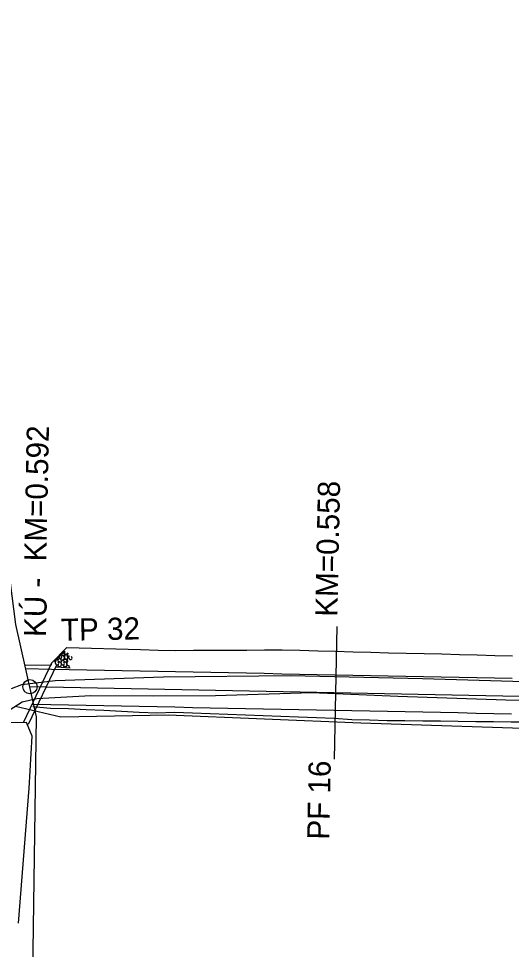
# Model space of a CAD drawing. Extents: x -478000 to -474772, y -1116940 to -1114124.
# Drawn here: x -477821.2 to -477765.6, y -1116669 to -1116563.9 of the extents above; entities that cross this region are included whole.
import ezdxf

# ---------------------------------------------------------------- set-up
doc = ezdxf.new("R2010")
doc.units = 0
for name, color, linetype in [('1', 7, 'Continuous'), ('hrana_P', 7, 'Continuous'), ('L', 7, 'Continuous'), ('ObPÚ', 7, 'Continuous'), ('POLYGONY_SITUACE_PF', 7, 'Continuous'), ('POLYGONY_SITUACE_PF_POPISY', 7, 'Continuous'), ('POLYGONY_SITUACE_PO', 7, 'Continuous'), ('popis', 7, 'Continuous'), ('TP_HS', 7, 'Continuous')]:
    doc.layers.add(name, color=color, linetype=linetype)

msp = doc.modelspace()

# ---------------------------------------------------------------- linework, layer by layer
at = {"layer": '1'}
for p, q in [((-477817.51878495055, -1116636.6520980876), (-477820.70846817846, -1116643.3293213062)), ((-477816.97738545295, -1116636.9107224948), (-477820.16706868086, -1116643.5879457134))]:
    msp.add_line(p, q, dxfattribs=at)
at = {"layer": 'hrana_P'}
for p, q in [((-477819.63, -1116641.574), (-477817.63300000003, -1116641.747)), ((-477817.63300000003, -1116641.747), (-477815.63400000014, -1116641.791)), ((-477815.63400000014, -1116641.791), (-477813.6350000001, -1116641.878)), ((-477813.6350000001, -1116641.878), (-477811.63700000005, -1116641.979)), ((-477811.63700000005, -1116641.979), (-477809.639, -1116642.0790000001)), ((-477809.639, -1116642.0790000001), (-477807.64, -1116642.179)), ((-477807.64, -1116642.179), (-477805.64200000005, -1116642.2790000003)), ((-477805.64200000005, -1116642.2790000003), (-477803.64, -1116642.2)), ((-477803.64, -1116642.2), (-477801.641, -1116642.2680000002)), ((-477801.641, -1116642.2680000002), (-477799.64200000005, -1116642.344)), ((-477799.64200000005, -1116642.344), (-477797.64300000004, -1116642.4200000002)), ((-477797.64300000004, -1116642.4200000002), (-477795.64400000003, -1116642.496)), ((-477795.64400000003, -1116642.496), (-477793.645, -1116642.5720000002)), ((-477793.645, -1116642.5720000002), (-477791.646, -1116642.649)), ((-477791.646, -1116642.649), (-477789.647, -1116642.725)), ((-477789.647, -1116642.725), (-477787.64900000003, -1116642.801)), ((-477787.64900000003, -1116642.801), (-477785.65, -1116642.877)), ((-477785.65, -1116642.877), (-477783.652, -1116643.0120000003)), ((-477783.652, -1116643.0120000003), (-477781.65300000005, -1116643.08)), ((-477781.65300000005, -1116643.08), (-477779.6530000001, -1116643.1230000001)), ((-477779.6530000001, -1116643.1230000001), (-477777.65300000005, -1116643.146)), ((-477777.65300000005, -1116643.146), (-477775.6539999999, -1116643.169)), ((-477775.6539999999, -1116643.169), (-477773.65400000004, -1116643.192)), ((-477773.65400000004, -1116643.192), (-477771.65400000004, -1116643.215)), ((-477771.65400000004, -1116643.215), (-477769.6539999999, -1116643.2350000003)), ((-477769.6539999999, -1116643.2350000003), (-477767.65400000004, -1116643.256)), ((-477767.65400000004, -1116643.256), (-477765.65400000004, -1116643.2720000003)), ((-477765.65400000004, -1116643.2720000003), (-477763.65300000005, -1116643.287))]:
    msp.add_line(p, q, dxfattribs=at)
for points in [[(-477817.51878495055, -1116636.6520980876), (-477815.8065033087, -1116634.8853385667)], [(-477815.8065033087, -1116634.8853385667), (-477807.499, -1116635.1430000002)], [(-477807.499, -1116635.1430000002), (-477805.5, -1116635.198)], [(-477805.5, -1116635.198), (-477803.5000000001, -1116635.222)], [(-477803.5000000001, -1116635.222), (-477801.499, -1116635.213)], [(-477801.499, -1116635.213), (-477799.4990000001, -1116635.205)], [(-477799.4990000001, -1116635.205), (-477797.498, -1116635.196)], [(-477797.498, -1116635.196), (-477795.498, -1116635.188)], [(-477795.498, -1116635.188), (-477793.49700000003, -1116635.179)], [(-477793.49700000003, -1116635.179), (-477791.49700000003, -1116635.171)], [(-477791.49700000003, -1116635.171), (-477789.4969999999, -1116635.217)], [(-477789.4969999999, -1116635.217), (-477787.498, -1116635.271)], [(-477787.498, -1116635.271), (-477785.498, -1116635.325)], [(-477785.498, -1116635.325), (-477783.499, -1116635.379)], [(-477783.499, -1116635.379), (-477781.5, -1116635.433)], [(-477781.5, -1116635.433), (-477779.5, -1116635.487)], [(-477779.5, -1116635.487), (-477777.50100000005, -1116635.542)], [(-477777.50100000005, -1116635.542), (-477775.5010000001, -1116635.577)], [(-477775.5010000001, -1116635.577), (-477773.50200000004, -1116635.6230000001)], [(-477773.50200000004, -1116635.6230000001), (-477771.503, -1116635.678)], [(-477771.503, -1116635.678), (-477769.503, -1116635.734)], [(-477769.503, -1116635.734), (-477767.504, -1116635.7890000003)], [(-477767.504, -1116635.7890000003), (-477765.505, -1116635.842)], [(-477820.5336913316, -1116636.8755662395), (-477817.5293924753, -1116636.8635490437)], [(-477817.54600000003, -1116637.369), (-477820.43502786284, -1116637.311190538)], [(-477815.54600000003, -1116637.409), (-477817.54600000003, -1116637.369)], [(-477817.5293924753, -1116636.8635490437), (-477817.51878495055, -1116636.6520980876)], [(-477817.51878495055, -1116636.6520980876), (-477817.51878495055, -1116636.6520980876)], [(-477817.51878495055, -1116636.6520980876), (-477817.51878495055, -1116636.6520980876)], [(-477813.54700000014, -1116637.45), (-477815.54600000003, -1116637.409)], [(-477811.547, -1116637.49), (-477813.54700000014, -1116637.45)], [(-477809.547, -1116637.53), (-477811.547, -1116637.49)], [(-477807.548, -1116637.57), (-477809.547, -1116637.53)], [(-477805.548, -1116637.6100000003), (-477807.548, -1116637.57)], [(-477803.549, -1116637.6500000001), (-477805.548, -1116637.6100000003)], [(-477801.5490000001, -1116637.69), (-477803.549, -1116637.6500000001)], [(-477799.549, -1116637.73), (-477801.5490000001, -1116637.69)], [(-477797.54999999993, -1116637.77), (-477799.549, -1116637.73)], [(-477795.55000000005, -1116637.81), (-477797.54999999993, -1116637.77)], [(-477793.55100000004, -1116637.85), (-477795.55000000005, -1116637.81)], [(-477791.55100000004, -1116637.89), (-477793.55100000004, -1116637.85)], [(-477789.5509999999, -1116637.9300000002), (-477791.55100000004, -1116637.89)], [(-477787.552, -1116637.97), (-477789.5509999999, -1116637.9300000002)], [(-477785.552, -1116638.01), (-477787.552, -1116637.97)], [(-477783.553, -1116638.05), (-477785.552, -1116638.01)], [(-477781.55300000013, -1116638.09), (-477783.553, -1116638.05)], [(-477779.553, -1116638.13), (-477781.55300000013, -1116638.09)], [(-477777.554, -1116638.171), (-477779.553, -1116638.13)], [(-477775.554, -1116638.211), (-477777.554, -1116638.171)], [(-477773.55500000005, -1116638.2510000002), (-477775.554, -1116638.211)], [(-477771.55500000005, -1116638.291), (-477773.55500000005, -1116638.2510000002)], [(-477769.5550000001, -1116638.331), (-477771.55500000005, -1116638.291)], [(-477767.55600000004, -1116638.371), (-477769.5550000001, -1116638.331)], [(-477765.55600000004, -1116638.411), (-477767.55600000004, -1116638.371)], [(-477817.62600000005, -1116641.369), (-477819.625, -1116641.3290000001)], [(-477815.62600000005, -1116641.409), (-477817.62600000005, -1116641.369)], [(-477813.62700000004, -1116641.449), (-477815.62600000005, -1116641.409)], [(-477811.62700000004, -1116641.489), (-477813.62700000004, -1116641.449)], [(-477809.6269999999, -1116641.5290000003), (-477811.62700000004, -1116641.489)], [(-477807.628, -1116641.569), (-477809.6269999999, -1116641.5290000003)], [(-477805.628, -1116641.609), (-477807.628, -1116641.569)], [(-477803.629, -1116641.649), (-477805.628, -1116641.609)], [(-477801.62900000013, -1116641.689), (-477803.629, -1116641.649)], [(-477799.6300000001, -1116641.729), (-477801.62900000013, -1116641.689)], [(-477797.63, -1116641.769), (-477799.6300000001, -1116641.729)], [(-477795.63, -1116641.809), (-477797.63, -1116641.769)], [(-477793.631, -1116641.8490000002), (-477795.63, -1116641.809)], [(-477791.631, -1116641.889), (-477793.631, -1116641.8490000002)], [(-477789.63200000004, -1116641.929), (-477791.631, -1116641.889)], [(-477787.63200000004, -1116641.969), (-477789.63200000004, -1116641.929)], [(-477785.63200000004, -1116642.01), (-477787.63200000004, -1116641.969)], [(-477783.6329999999, -1116642.05), (-477785.63200000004, -1116642.01)], [(-477781.63300000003, -1116642.09), (-477783.6329999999, -1116642.05)], [(-477779.634, -1116642.13), (-477781.63300000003, -1116642.09)], [(-477777.634, -1116642.1700000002), (-477779.634, -1116642.13)], [(-477775.634, -1116642.21), (-477777.634, -1116642.1700000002)], [(-477773.635, -1116642.25), (-477775.634, -1116642.21)], [(-477771.635, -1116642.29), (-477773.635, -1116642.25)], [(-477769.636, -1116642.33), (-477771.635, -1116642.29)], [(-477767.6360000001, -1116642.3700000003), (-477769.636, -1116642.33)], [(-477765.63599999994, -1116642.4100000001), (-477767.6360000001, -1116642.3700000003)]]:
    msp.add_lwpolyline(points, dxfattribs=at)
at = {"layer": 'L'}
for p, q in [((-477820.37, -1116643.3530000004), (-477822.248, -1116643.399)), ((-477819.727, -1116644.911), (-477820.37, -1116643.3530000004)), ((-477820.049, -1116650.783), (-477819.727, -1116644.911)), ((-477821.256, -1116665.994), (-477820.049, -1116650.783))]:
    msp.add_line(p, q, dxfattribs=at)
for points in [[(-477822.03574678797, -1116639.5246735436), (-477820.897, -1116639.077), (-477817.125, -1116638.639), (-477804.88800000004, -1116638.219), (-477790.55500000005, -1116638.041), (-477775.668, -1116638.394), (-477759.069, -1116638.902), (-477743.411, -1116638.9100000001), (-477727.375, -1116639.612), (-477703.506, -1116640.58), (-477689.085, -1116640.739), (-477662.498, -1116640.639)], [(-477662.06200000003, -1116642.877), (-477676.23600000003, -1116643.067), (-477687.02, -1116643.1700000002), (-477697.63300000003, -1116643.0990000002), (-477704.81, -1116643.051), (-477715.494, -1116642.494), (-477726.12200000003, -1116642.2620000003), (-477735.31700000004, -1116641.85), (-477743.53400000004, -1116641.717), (-477756.732, -1116641.027), (-477766.265, -1116640.857), (-477778.44700000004, -1116640.4440000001), (-477788.169, -1116640.0050000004), (-477799.01300000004, -1116640.338), (-477806.00200000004, -1116640.405), (-477813.109, -1116640.341), (-477819.206, -1116640.6970000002), (-477820.85500000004, -1116641.0690000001), (-477822.30500000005, -1116642.0150000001)], [(-477619.515, -1116641.5785000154), (-477631.233, -1116645.709), (-477649.971, -1116646.3930000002), (-477673.38300000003, -1116646.6570000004), (-477700.23000000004, -1116645.8), (-477732.117, -1116644.5820000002), (-477759.787, -1116644.2), (-477782.63, -1116643.433), (-477804.353, -1116642.533), (-477816.493, -1116642.756), (-477821.58, -1116641.5420000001)]]:
    msp.add_lwpolyline(points, dxfattribs=at)
at = {"layer": 'ObPÚ'}
msp.add_lwpolyline([(-477835.42000000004, -1116846.57), (-477827.27, -1116742.4300000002), (-477820.03, -1116698.07), (-477819.21, -1116642.72), (-477821.57, -1116632.3), (-477837.97000000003, -1116504.33), (-477857.08, -1116470.6500000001), (-477873.54000000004, -1116443.03), (-477876.37, -1116437.54), (-477908.62, -1116376.53), (-477932.52, -1116347.32), (-477968.13, -1116341.56), (-477983.23000000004, -1116329.55), (-478000.09, -1116315.6100000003), (-477992.63, -1116266.4000000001), (-477967.7, -1116217.95), (-477949.03, -1116186.01), (-477915.97000000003, -1116136), (-477827.83, -1116006.6), (-477791.07, -1115962.29), (-477744.4, -1115881.63), (-477737.43000000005, -1115839.5), (-477657.26, -1115725.45)], dxfattribs=at)
at = {"layer": 'POLYGONY_SITUACE_PF'}
msp.add_lwpolyline([(-477785.59642095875, -1116647.511332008), (-477785.4462150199, -1116640.012836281), (-477785.2960090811, -1116632.514340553)], dxfattribs=at)
at = {"layer": 'POLYGONY_SITUACE_PO'}
msp.add_lwpolyline([(-477500.70781559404, -1116571.337971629), (-477504.2169244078, -1116571.341618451), (-477507.59721562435, -1116572.283684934), (-477510.60239086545, -1116574.095529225), (-477513.0134838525, -1116576.645134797), (-477523.43050248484, -1116591.171911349), (-477530.00477229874, -1116599.187289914), (-477537.5603201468, -1116606.285248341), (-477545.97027502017, -1116612.3465993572), (-477555.0934189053, -1116617.269562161), (-477583.0835182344, -1116630.106284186), (-477594.8330191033, -1116634.7625948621), (-477607.0070808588, -1116638.15732904), (-477619.47066272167, -1116640.252830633), (-477632.0855124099, -1116641.025855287), (-477697.0704420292, -1116641.579382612), (-477701.8281190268, -1116641.597270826), (-477706.5857508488, -1116641.569887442), (-477711.3429067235, -1116641.4972349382), (-477819.96178678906, -1116639.321438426)], dxfattribs=at)
msp.add_circle((-477819.96178678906, -1116639.321438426), 0.8, dxfattribs=at)
at = {"layer": 'TP_HS'}
for p, q in [((-477817.1992335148, -1116636.5292330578), (-477816.0219658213, -1116635.3150638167)), ((-477816.9724906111, -1116637.0847397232), (-477815.41556718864, -1116637.1836571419))]:
    msp.add_line(p, q, dxfattribs=at)
for points in [[(-477816.6534792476, -1116636.2622268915), (-477816.87071417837, -1116636.3424783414), (-477816.6687195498, -1116636.4792448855), (-477816.5380370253, -1116636.5733563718), (-477816.4110612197, -1116636.4122001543), (-477816.49953114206, -1116636.296191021)], [(-477816.7210451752, -1116636.0360558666), (-477816.7077199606, -1116636.0461750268), (-477816.69413039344, -1116636.0560148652), (-477816.66639387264, -1116636.074459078), (-477816.610340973, -1116636.1036231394), (-477816.5566571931, -1116636.1171880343), (-477816.531882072, -1116636.1161332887), (-477816.5202174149, -1116636.113298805), (-477816.51459158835, -1116636.1112613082), (-477816.51183352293, -1116636.1100820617), (-477816.5091132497, -1116636.1087937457), (-477816.4861330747, -1116636.09641658), (-477816.45969568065, -1116636.0801020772), (-477816.40689431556, -1116636.0389251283), (-477816.3715993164, -1116635.991791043), (-477816.36704487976, -1116635.9680301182), (-477816.36918335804, -1116635.9564581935), (-477816.37149932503, -1116635.950793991), (-477816.37470084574, -1116635.9452279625), (-477816.4869317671, -1116635.7760886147)], [(-477816.12688610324, -1116635.8731525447), (-477816.11342905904, -1116636.0874483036), (-477816.2381202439, -1116636.3267777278), (-477816.4558505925, -1116636.2937516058), (-477816.4233301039, -1116636.0793547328)], [(-477816.40060304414, -1116635.7055694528), (-477816.38289023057, -1116635.7140070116), (-477816.36654905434, -1116635.722304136), (-477816.352027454, -1116635.730409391), (-477816.3455889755, -1116635.734373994), (-477816.33977336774, -1116635.7382713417), (-477816.3070025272, -1116635.7622914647), (-477816.2740854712, -1116635.787224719), (-477816.24134173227, -1116635.8112091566), (-477816.2251347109, -1116635.8222637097), (-477816.2170898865, -1116635.8274547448), (-477816.2130843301, -1116635.8299534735), (-477816.2090908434, -1116635.8323828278), (-477816.2038416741, -1116635.8349365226), (-477816.1982799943, -1116635.836530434), (-477816.1863771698, -1116635.8370269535), (-477816.1605601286, -1116635.8285711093), (-477816.10973222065, -1116635.7843945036), (-477816.0768396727, -1116635.7239230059), (-477816.07344183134, -1116635.6950985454), (-477816.0761114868, -1116635.6823554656), (-477816.0786767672, -1116635.6765657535), (-477816.08211503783, -1116635.67122661), (-477816.17058496, -1116635.5552174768)], [(-477816.00397520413, -1116636.2632415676), (-477816.2212101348, -1116636.3434930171), (-477816.0192155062, -1116636.4802595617), (-477815.8885329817, -1116636.5743710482), (-477815.76155717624, -1116636.4132148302), (-477815.8500270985, -1116636.297205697)], [(-477816.15404885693, -1116635.451287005), (-477816.1439567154, -1116635.4507018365), (-477816.1341824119, -1116635.44909511), (-477816.12475821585, -1116635.4464123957), (-477816.1201874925, -1116635.4446505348), (-477816.1157163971, -1116635.442599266), (-477816.0927362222, -1116635.4302221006), (-477816.0860261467, -1116635.4263073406), (-477816.07940530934, -1116635.4222597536), (-477816.07284057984, -1116635.4181147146), (-477816.06629882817, -1116635.4139075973), (-477816.05250713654, -1116635.4044592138), (-477816.03921987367, -1116635.3943899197), (-477816.02627174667, -1116635.383785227), (-477816.0198732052, -1116635.378308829), (-477816.01349746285, -1116635.372730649), (-477816.0008836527, -1116635.3602234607)], [(-477815.977258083, -1116635.7753499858), (-477816.084855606, -1116635.9252952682), (-477816.02384745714, -1116636.129115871), (-477815.8089553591, -1116636.2041623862), (-477815.67454295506, -1116636.040596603), (-477815.7867738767, -1116635.8714572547)], [(-477815.7428335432, -1116635.5217900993), (-477815.7531978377, -1116635.5418097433), (-477815.7648286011, -1116635.5612907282), (-477815.7907119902, -1116635.598188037), (-477815.8181286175, -1116635.6315846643), (-477815.8316759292, -1116635.6466897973), (-477815.8382805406, -1116635.6537949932), (-477815.844723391, -1116635.660583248), (-477815.84927649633, -1116635.664760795), (-477815.89897927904, -1116635.6851269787), (-477815.9743278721, -1116635.6886179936), (-477816.03930681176, -1116635.669835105), (-477816.0580756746, -1116635.6517093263), (-477816.0623093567, -1116635.6403960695), (-477816.06292343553, -1116635.6341685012), (-477816.0624537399, -1116635.627557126), (-477816.0299332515, -1116635.4131602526)], [(-477815.62437517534, -1116635.616621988), (-477815.8416101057, -1116635.6968734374), (-477815.84792832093, -1116635.6996134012), (-477815.85263452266, -1116635.702543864), (-477815.85752974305, -1116635.7089396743), (-477815.85148343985, -1116635.7236145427), (-477815.79389976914, -1116635.758446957), (-477815.70967260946, -1116635.7966842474), (-477815.6535693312, -1116635.8247774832), (-477815.64620270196, -1116635.8292507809), (-477815.6396154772, -1116635.8336399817), (-477815.6158634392, -1116635.850900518), (-477815.59198824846, -1116635.8689108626)], [(-477815.6705049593, -1116636.449873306), (-477815.6795973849, -1116636.4486863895), (-477815.6884576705, -1116636.4471619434), (-477815.7052501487, -1116636.443091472), (-477815.7335010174, -1116636.4308012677), (-477815.7515507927, -1116636.4128588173), (-477815.7555919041, -1116636.401723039), (-477815.7561638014, -1116636.3956061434), (-477815.7556927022, -1116636.389120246), (-477815.72317221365, -1116636.1747233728)], [(-477815.5092308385, -1116635.826274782), (-477815.6168283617, -1116635.976220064), (-477815.55582021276, -1116636.1800406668), (-477815.3409281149, -1116636.2550871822), (-477815.20651571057, -1116636.0915213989), (-477815.3187466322, -1116635.9223820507)], [(-477817.00636215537, -1116636.4209548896), (-477817.1139596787, -1116636.570900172), (-477817.05295152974, -1116636.774720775), (-477816.8380594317, -1116636.84976729), (-477816.7036470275, -1116636.6862015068), (-477816.81587794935, -1116636.5170621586)], [(-477816.45583228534, -1116636.614126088), (-477816.4423752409, -1116636.828421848), (-477816.56706642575, -1116637.067751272), (-477816.7847967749, -1116637.0347251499), (-477816.75227628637, -1116636.8203282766)], [(-477816.3568581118, -1116636.4219695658), (-477816.4644556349, -1116636.5719148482), (-477816.4034474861, -1116636.7757354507), (-477816.1885553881, -1116636.8507819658), (-477816.05414298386, -1116636.6872161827), (-477816.1663739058, -1116636.5180768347)], [(-477815.80632824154, -1116636.6151407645), (-477815.7928711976, -1116636.8294365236), (-477815.9175623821, -1116637.068765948), (-477816.1352927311, -1116637.0357398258), (-477816.10277224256, -1116636.8213429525)], [(-477815.7218112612, -1116636.5182957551), (-477815.8294087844, -1116636.6682410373), (-477815.8330594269, -1116636.6737478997), (-477815.83626475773, -1116636.6794552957), (-477815.84137419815, -1116636.6914137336), (-477815.8466311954, -1116636.7170995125), (-477815.8392416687, -1116636.772301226), (-477815.8116836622, -1116636.8264279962), (-477815.7917300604, -1116636.8507700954), (-477815.78045261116, -1116636.8618551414), (-477815.77451909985, -1116636.867075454), (-477815.76840063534, -1116636.8720616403), (-477815.74122328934, -1116636.8924159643), (-477815.71315310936, -1116636.9112931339), (-477815.65630039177, -1116636.941299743), (-477815.6017747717, -1116636.9554489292), (-477815.5766134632, -1116636.9545043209), (-477815.56477323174, -1116636.9516645), (-477815.5535085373, -1116636.9471081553), (-477815.54086087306, -1116636.9405153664), (-477815.5267017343, -1116636.9325045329)], [(-477815.4512939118, -1116637.1855876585), (-477815.4625514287, -1116637.1816041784), (-477815.47271379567, -1116637.1768618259), (-477815.47708201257, -1116637.1743873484), (-477815.4812151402, -1116637.1716276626), (-477815.48517091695, -1116637.168537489), (-477815.489007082, -1116637.165071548), (-477815.4921199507, -1116637.1617077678), (-477815.4947594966, -1116637.1581015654), (-477815.4969415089, -1116637.154252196), (-477815.49868177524, -1116637.1501589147), (-477815.49992397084, -1116637.1458865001), (-477815.50057090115, -1116637.141513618), (-477815.5006968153, -1116637.136890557), (-477815.50024588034, -1116637.1320660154), (-477815.48911188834, -1116637.0586632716)]]:
    msp.add_spline(points, degree=3, dxfattribs=at)

# ---------------------------------------------------------------- texts
at = {"layer": 'POLYGONY_SITUACE_PF_POPISY'}
for s, p in [('KM=0.592', (-477818.11876562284, -1116625.2029290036)), ('KM=0.558', (-477785.2746090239, -1116631.4460190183)), ('KÚ - ', (-477818.1522844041, -1116633.7330598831)), ('PF 16', (-477786.1945886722, -1116656.6007371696))]:
    msp.add_text(s, height=2.5, rotation=88.85243443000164, dxfattribs=at).set_placement(p)
at = {"layer": 'popis'}
msp.add_text('TP 32', height=2.5000000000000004, rotation=1.1485397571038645, dxfattribs=at).set_placement((-477816.4458126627, -1116634.158432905))

doc.saveas('drawing.dxf')
